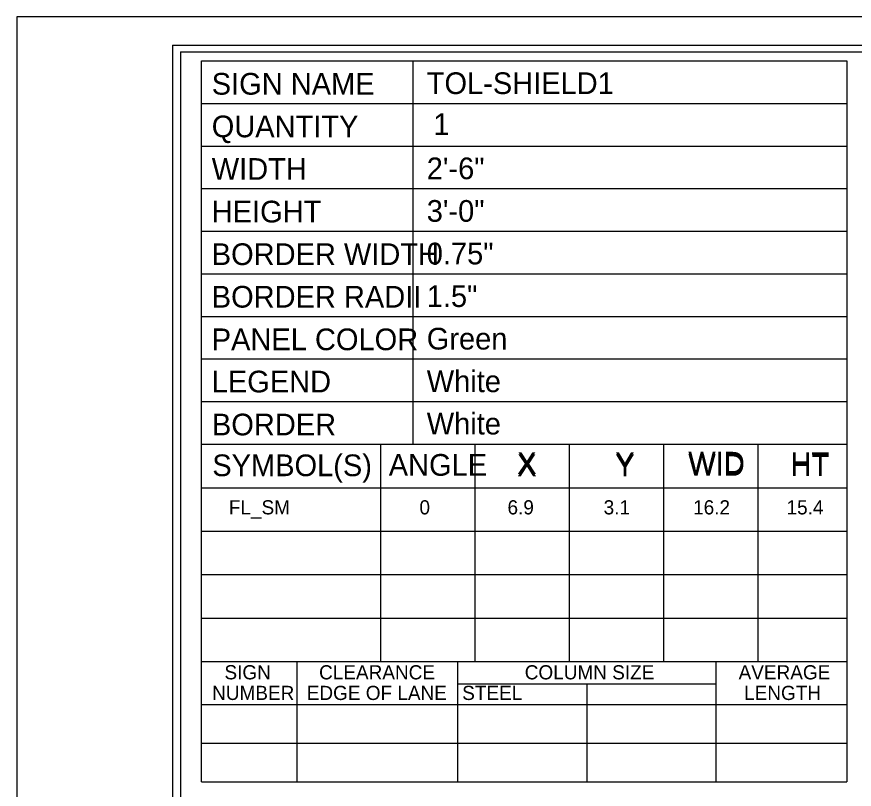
# Model space of a CAD drawing. Extents: x 17890628 to 17890844, y 17897693 to 17898031.
# Drawn here: x 17890700.47 to 17890726.2, y 17897976.07 to 17897999.81 of the extents above; entities that cross this region are included whole.
import ezdxf

# ---------------------------------------------------------------- set-up
doc = ezdxf.new("R2010")
doc.units = 0
for name, color, linetype in [('GSSign', 7, 'Continuous'), ('PlotBorder_dp', 7, 'Continuous'), ('SheetBorder_dp', 7, 'Continuous'), ('SheetLinesMisc2_dp', 7, 'Continuous'), ('TextMinor', 7, 'Continuous')]:
    doc.layers.add(name, color=color, linetype=linetype)

msp = doc.modelspace()

# ---------------------------------------------------------------- linework, layer by layer
at = {"layer": 'PlotBorder_dp'}
msp.add_lwpolyline([(17890700.471, 17897907.61), (17890843.989, 17897907.61), (17890843.989, 17897999.809), (17890700.471, 17897999.809)], close=True, dxfattribs=at)
at = {"layer": 'SheetBorder_dp'}
for q in [(17890705.254, 17897908.479), (17890839.205, 17897998.94)]:
    msp.add_line((17890705.254, 17897998.94), q, dxfattribs=at)
at = {"layer": 'SheetLinesMisc2_dp'}
for p, q in [((17890705.5, 17897998.732), (17890839.233, 17897998.732)), ((17890705.5, 17897998.732), (17890705.5, 17897915.484)), ((17890706.142, 17897976.3), (17890706.142, 17897998.455)), ((17890706.142, 17897998.455), (17890725.973, 17897998.455)), ((17890712.643, 17897998.455), (17890712.643, 17897986.674)), ((17890725.973, 17897998.455), (17890725.973, 17897976.3)), ((17890706.142, 17897997.146), (17890725.973, 17897997.146)), ((17890706.142, 17897995.837), (17890725.973, 17897995.837)), ((17890706.142, 17897994.529), (17890725.973, 17897994.529)), ((17890706.142, 17897993.22), (17890725.973, 17897993.22)), ((17890706.142, 17897991.911), (17890725.973, 17897991.911)), ((17890706.142, 17897990.603), (17890725.973, 17897990.603)), ((17890706.142, 17897989.294), (17890716.057, 17897989.294)), ((17890716.057, 17897989.294), (17890725.973, 17897989.294)), ((17890706.142, 17897987.986), (17890716.057, 17897987.986)), ((17890716.057, 17897987.986), (17890725.973, 17897987.986)), ((17890706.141, 17897986.674), (17890725.973, 17897986.674)), ((17890711.644, 17897986.674), (17890711.644, 17897979.993)), ((17890714.542, 17897986.674), (17890714.542, 17897979.993)), ((17890717.44, 17897986.674), (17890717.44, 17897979.993)), ((17890720.337, 17897986.674), (17890720.337, 17897979.993)), ((17890723.235, 17897986.674), (17890723.235, 17897979.993)), ((17890706.141, 17897985.338), (17890725.973, 17897985.338)), ((17890706.141, 17897984.002), (17890725.973, 17897984.002)), ((17890706.141, 17897982.666), (17890725.973, 17897982.666)), ((17890706.141, 17897981.329), (17890725.973, 17897981.329)), ((17890706.141, 17897979.993), (17890725.973, 17897979.993)), ((17890709.08, 17897979.993), (17890709.08, 17897976.3)), ((17890714.015, 17897979.993), (17890714.015, 17897976.3)), ((17890721.947, 17897979.993), (17890721.947, 17897976.3)), ((17890714.015, 17897979.313), (17890721.947, 17897979.313)), ((17890717.981, 17897979.313), (17890717.981, 17897976.3)), ((17890706.141, 17897978.673), (17890725.973, 17897978.673)), ((17890706.141, 17897977.487), (17890725.973, 17897977.487)), ((17890706.142, 17897976.3), (17890725.973, 17897976.3))]:
    msp.add_line(p, q, dxfattribs=at)

# ---------------------------------------------------------------- texts
at = {"layer": 'GSSign'}
for s, height, p in [('TOL-SHIELD1', 0.66667, (17890713.067, 17897997.434)), ('1', 0.667, (17890713.27, 17897996.176)), ('2\'-6"', 0.6667, (17890713.067, 17897994.817)), ('3\'-0"', 0.6667, (17890713.067, 17897993.509)), ('0.75"', 0.6667, (17890713.067, 17897992.2)), ('1.5"', 0.6667, (17890713.067, 17897990.891)), ('Green', 0.6667, (17890713.067, 17897989.583)), ('White', 0.6667, (17890713.067, 17897988.274)), ('White', 0.6667, (17890713.067, 17897986.973)), ('X', 0.667, (17890715.845, 17897985.76)), ('Y', 0.667, (17890718.858, 17897985.76)), ('WID', 0.6667, (17890721.102, 17897985.774)), ('HT', 0.6667, (17890724.243, 17897985.761)), ('FL_SM', 0.4357, (17890706.987, 17897984.517)), ('0', 0.436, (17890712.843, 17897984.517)), ('6.9', 0.4357, (17890715.548, 17897984.517)), ('3.1', 0.4357, (17890718.501, 17897984.517)), ('16.2', 0.4357, (17890721.25, 17897984.517)), ('15.4', 0.4357, (17890724.121, 17897984.517))]:
    msp.add_text(s, height=height, dxfattribs=at).set_placement(p)
at = {"layer": 'TextMinor'}
for s, height, p in [('SIGN NAME', 0.6667, (17890706.461, 17897997.415)), ('QUANTITY', 0.6667, (17890706.461, 17897996.106)), ('WIDTH', 0.6667, (17890706.461, 17897994.798)), ('HEIGHT', 0.6667, (17890706.461, 17897993.489)), ('BORDER WIDTH', 0.66667, (17890706.461, 17897992.18)), ('BORDER RADII', 0.66667, (17890706.461, 17897990.872)), ('PANEL COLOR', 0.66667, (17890706.461, 17897989.563)), ('LEGEND', 0.6667, (17890706.461, 17897988.266)), ('BORDER', 0.6667, (17890706.467, 17897986.946)), ('SYMBOL(S)', 0.6667, (17890706.478, 17897985.692)), ('ANGLE', 0.6667, (17890711.899, 17897985.705)), ('X', 0.667, (17890715.846, 17897985.692)), ('Y', 0.667, (17890718.859, 17897985.692)), ('WID', 0.6667, (17890721.103, 17897985.705)), ('HT', 0.6667, (17890724.244, 17897985.693)), ('SIGN', 0.4357, (17890706.852, 17897979.448)), ('CLEARANCE', 0.4357, (17890709.759, 17897979.447)), ('COLUMN SIZE', 0.43573, (17890716.077, 17897979.447)), ('AVERAGE', 0.4357, (17890722.648, 17897979.447)), ('NUMBER', 0.4357, (17890706.473, 17897978.814)), ('EDGE OF LANE', 0.43573, (17890709.38, 17897978.814)), ('STEEL    ', 0.4357, (17890714.156, 17897978.814)), ('LENGTH', 0.4357, (17890722.817, 17897978.814))]:
    msp.add_text(s, height=height, dxfattribs=at).set_placement(p)

doc.saveas('drawing.dxf')
